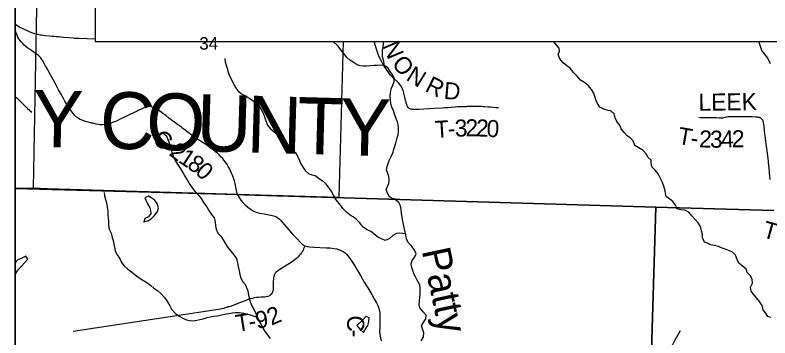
# Model space of a CAD drawing. Extents: x 0 to 34, y 0 to 22.
# Drawn here: x 1.631 to 4.145, y 15.676 to 16.751 of the extents above; entities that cross this region are included whole.
import ezdxf

# ---------------------------------------------------------------- set-up
doc = ezdxf.new("R2010")
doc.units = 0
for name, color, linetype in [('GM_X_Corporation', 7, 'Continuous'), ('GM_X_County_Road', 7, 'Continuous'), ('GM_X_County_Road_Text', 7, 'Continuous'), ('GM_X_County_Text', 7, 'Continuous'), ('GM_X_Minor_Lake', 7, 'Continuous'), ('GM_X_Minor_River', 7, 'Continuous'), ('GM_X_Minor_River_Text', 7, 'Continuous'), ('GM_X_Section_Text', 7, 'Continuous'), ('GM_X_Township_Road', 7, 'Continuous'), ('GM_X_Township_Road_Text', 7, 'Continuous'), ('SH_Data', 7, 'Continuous'), ('SH_Text', 7, 'Continuous')]:
    doc.layers.add(name, color=color, linetype=linetype)

msp = doc.modelspace()

# ---------------------------------------------------------------- linework, layer by layer
at = {"layer": 'GM_X_Corporation'}
for points in [[(8.4311, 21.3734), (1.6311, 21.3734), (1.6311, 16.1731), (2.3716, 16.1532), (2.3935, 16.1523), (3.7652, 16.1115), (4.1576, 16.1007)], [(4.7823, 18.128), (4.0508, 18.1454), (3.7812, 18.1547), (3.7776, 18.3354), (3.7807, 18.4204), (3.7875, 18.9248), (3.7889, 19.1658), (3.7877, 19.187), (3.1142, 19.2057), (2.7749, 19.2162), (2.7798, 20.0198), (2.7831, 20.242), (2.7976, 21.3075), (2.7987, 21.3734), (1.6311, 21.3734), (1.6311, 16.1731), (2.3716, 16.1532), (2.3935, 16.1523), (3.7652, 16.1115), (4.1576, 16.1007)], [(2.7241, 16.6637), (2.7088, 16.1431), (1.7396, 16.1729), (1.6922, 16.1742), (1.7115, 17.1949), (1.8974, 17.1907)], [(4.1576, 16.1007), (3.7652, 16.1115), (2.3935, 16.1523), (2.3716, 16.1532), (1.6311, 16.1731), (1.6311, 14.5734), (8.4311, 14.5734)], [(4.1576, 16.1007), (3.7652, 16.1115), (3.7495, 15.5967), (3.7461, 15.4826), (3.7459, 15.4785), (3.7348, 15.1121), (3.7347, 15.1105), (3.7221, 14.5734), (8.4311, 14.5734)]]:
    msp.add_lwpolyline(points, dxfattribs=at)
for points in [[(1.6311, 17.1972), (1.6311, 16.1758), (1.6922, 16.1742), (1.7115, 17.1949)], [(1.6311, 16.1731), (1.6311, 14.5734), (3.7221, 14.5734), (3.7347, 15.1105), (3.7348, 15.1121), (3.7459, 15.4785), (3.7461, 15.4826), (3.7495, 15.5967), (3.7652, 16.1115), (2.3935, 16.1523), (2.3716, 16.1532)]]:
    msp.add_lwpolyline(points, close=True, dxfattribs=at)
at = {"layer": 'GM_X_County_Road'}
for points in [[(1.6311, 16.7219), (1.6337, 16.7197), (1.6386, 16.716), (1.6433, 16.713), (1.6493, 16.7097), (1.6543, 16.7072), (1.6633, 16.703), (1.6718, 16.6993), (1.6799, 16.6959), (1.6886, 16.6926), (1.6962, 16.6901), (1.7028, 16.6883), (1.7095, 16.6869), (1.715, 16.6858), (1.7187, 16.6852), (1.7236, 16.6845), (1.7309, 16.6835), (1.7452, 16.6821), (1.7544, 16.6814), (1.7606, 16.6809), (1.7686, 16.6801), (1.776, 16.6794), (1.7835, 16.6787), (1.7927, 16.6778), (1.81, 16.6762), (1.8242, 16.6751), (1.8291, 16.6748), (1.8445, 16.6739), (1.8974, 16.6716)], [(2.3718, 16.1526), (2.3706, 16.1576), (2.3696, 16.1624), (2.3687, 16.1672), (2.3678, 16.172), (2.3668, 16.1775), (2.3654, 16.1842), (2.364, 16.1902), (2.3616, 16.1988), (2.3564, 16.2141), (2.3542, 16.2197), (2.3521, 16.2249), (2.3486, 16.2328), (2.345, 16.2401), (2.3411, 16.2471), (2.3373, 16.2535), (2.3324, 16.2607), (2.3268, 16.2682), (2.3228, 16.2729), (2.3178, 16.2784), (2.3123, 16.2843), (2.3064, 16.2898), (2.2988, 16.2962), (2.291, 16.3024), (2.2836, 16.308), (2.2734, 16.3151), (2.2626, 16.3222), (2.2518, 16.3292), (2.2471, 16.3322), (2.2418, 16.3354), (2.2344, 16.3401), (2.2269, 16.3455), (2.221, 16.35), (2.2195, 16.3512), (2.2077, 16.3603), (2.1929, 16.3716), (2.1869, 16.3761), (2.1849, 16.3775), (2.1758, 16.384), (2.1732, 16.3858), (2.1604, 16.3953), (2.1565, 16.3983), (2.151, 16.4024), (2.1436, 16.408), (2.1327, 16.4163), (2.1237, 16.423), (2.1132, 16.4306), (2.105, 16.4362), (2.097, 16.4411), (2.0932, 16.443), (2.088, 16.445), (2.0857, 16.4457), (2.0796, 16.4466), (2.076, 16.4466), (2.0722, 16.4462), (2.0662, 16.4445), (2.0622, 16.443), (2.0542, 16.4394), (2.0458, 16.4354), (2.0407, 16.433), (2.0374, 16.4313), (2.0128, 16.4196), (1.9972, 16.4118), (1.9816, 16.4041), (1.9686, 16.3982), (1.9594, 16.3944), (1.9524, 16.3918), (1.9453, 16.3896), (1.9381, 16.3878), (1.9307, 16.3865), (1.9227, 16.3859), (1.9146, 16.386), (1.9084, 16.3867), (1.9011, 16.388), (1.8896, 16.3906), (1.8854, 16.3917), (1.8829, 16.3922), (1.8697, 16.3955), (1.8619, 16.3979), (1.8543, 16.4006), (1.8475, 16.4035), (1.8426, 16.4062), (1.8381, 16.4095), (1.8348, 16.4123), (1.83, 16.4171), (1.8255, 16.4223), (1.821, 16.4282), (1.8156, 16.4358), (1.809, 16.4456), (1.8037, 16.454), (1.7973, 16.4647), (1.7923, 16.4732), (1.7876, 16.4813), (1.7852, 16.4856), (1.7761, 16.5025), (1.7705, 16.5129), (1.7658, 16.5217), (1.7533, 16.5446), (1.7491, 16.5522), (1.74, 16.5685), (1.737, 16.5739), (1.7352, 16.5772), (1.7339, 16.5793), (1.7279, 16.5901), (1.7223, 16.5998), (1.7211, 16.6019), (1.7184, 16.6061), (1.7157, 16.6095), (1.7128, 16.6127), (1.7087, 16.6165), (1.7028, 16.621), (1.6952, 16.6264), (1.691, 16.6291), (1.6808, 16.636), (1.6737, 16.641), (1.6669, 16.6463), (1.6614, 16.6512), (1.6565, 16.656), (1.6511, 16.662), (1.6466, 16.6679), (1.644, 16.6721), (1.6408, 16.678), (1.6379, 16.6842), (1.6338, 16.6939), (1.6311, 16.7007)], [(2.3718, 16.1526), (2.3828, 16.1351), (2.3899, 16.1265), (2.3974, 16.1186), (2.4068, 16.1109), (2.417, 16.1039), (2.4241, 16.0994), (2.4309, 16.0963), (2.437, 16.0938), (2.4456, 16.0915), (2.4526, 16.0901), (2.4607, 16.0887), (2.483, 16.0849), (2.4915, 16.083), (2.499, 16.08), (2.5057, 16.076), (2.5103, 16.0726), (2.5156, 16.068), (2.5219, 16.0608), (2.5426, 16.0363), (2.5555, 16.0217), (2.5714, 16.0044), (2.5804, 15.9947), (2.5856, 15.9897), (2.5889, 15.9867), (2.5921, 15.9844), (2.5956, 15.9825), (2.6039, 15.9803), (2.6115, 15.9794), (2.6265, 15.9781), (2.6673, 15.9761), (2.6738, 15.9758), (2.6806, 15.9754), (2.6931, 15.9741), (2.7026, 15.9722), (2.711, 15.9695), (2.7196, 15.9661), (2.7242, 15.9634), (2.7301, 15.959), (2.7352, 15.9545), (2.7398, 15.9495), (2.7443, 15.9437), (2.7494, 15.9362), (2.7533, 15.9297), (2.7621, 15.9155), (2.7716, 15.9), (2.7812, 15.884), (2.794, 15.8618), (2.8054, 15.8424), (2.819, 15.8206), (2.8286, 15.8038), (2.8347, 15.7931), (2.8393, 15.7836), (2.8416, 15.7777), (2.8437, 15.7709), (2.8451, 15.7647), (2.8459, 15.7578), (2.8462, 15.7527), (2.846, 15.7402), (2.8459, 15.7276), (2.8454, 15.7113), (2.8452, 15.6969), (2.8459, 15.687), (2.8476, 15.676), (2.8508, 15.6658)]]:
    msp.add_lwpolyline(points, dxfattribs=at)
at = {"layer": 'GM_X_Minor_Lake'}
for points in [[(2.0633, 16.142), (2.0717, 16.1227), (2.0797, 16.1095), (2.0821, 16.0997), (2.0833, 16.0899), (2.0754, 16.0792), (2.0634, 16.0734), (2.0597, 16.0617), (2.067, 16.0642)], [(2.067, 16.0642), (2.0732, 16.0663), (2.0845, 16.0728), (2.0966, 16.085), (2.1059, 16.0972), (2.1092, 16.1094), (2.1039, 16.123), (2.0943, 16.1373), (2.0848, 16.1429), (2.0753, 16.1478), (2.0633, 16.142)], [(1.6715, 15.9409), (1.6671, 15.9479), (1.6532, 15.9417), (1.6404, 15.9359), (1.6311, 15.9263)], [(1.6311, 15.8867), (1.6316, 15.8874), (1.6406, 15.9011), (1.653, 15.9144), (1.6639, 15.9266), (1.6732, 15.9381), (1.6715, 15.9409)], [(2.7946, 15.6999), (2.7971, 15.7042), (2.8054, 15.7171), (2.8095, 15.7304), (2.8099, 15.7425), (2.7996, 15.7471), (2.7883, 15.7349), (2.7698, 15.717)], [(2.7698, 15.717), (2.7805, 15.7041), (2.7915, 15.6943), (2.7946, 15.6999)]]:
    msp.add_lwpolyline(points, dxfattribs=at)
at = {"layer": 'GM_X_Minor_River'}
for points in [[(2.8995, 16.1342), (2.898, 16.1378), (2.8881, 16.1407), (2.8782, 16.1456), (2.871, 16.1577), (2.8671, 16.1706), (2.8716, 16.1801), (2.876, 16.19), (2.8775, 16.2029), (2.8762, 16.2131), (2.8724, 16.2233), (2.8681, 16.2362), (2.8707, 16.2472), (2.8737, 16.2568), (2.8766, 16.2666), (2.8837, 16.28), (2.8901, 16.2945), (2.893, 16.304), (2.896, 16.3142), (2.9001, 16.3291), (2.9041, 16.3428), (2.9067, 16.3538), (2.9081, 16.3644), (2.9077, 16.3777), (2.9053, 16.3917), (2.9006, 16.4069), (2.896, 16.4175), (2.8917, 16.4318), (2.8856, 16.4447), (2.8828, 16.4553), (2.8816, 16.4678), (2.8804, 16.4799), (2.8818, 16.4917), (2.8832, 16.505), (2.8896, 16.5176), (2.8941, 16.5298), (2.894, 16.5415), (2.8897, 16.5514), (2.8802, 16.563), (2.8721, 16.5755), (2.8607, 16.583), (2.8467, 16.584), (2.8372, 16.5836), (2.827, 16.5831), (2.8137, 16.5819), (2.8031, 16.581), (2.7917, 16.5805), (2.7807, 16.582), (2.7701, 16.5857), (2.7575, 16.5943), (2.7461, 16.6014), (2.7365, 16.6097), (2.7266, 16.6225), (2.7163, 16.635), (2.7067, 16.6474), (2.6906, 16.6637)], [(2.8603, 16.583), (2.8603, 16.5887), (2.8587, 16.5982), (2.8544, 16.6118), (2.855, 16.6323), (2.8572, 16.6467), (2.8591, 16.6637)], [(3.8348, 16.1094), (3.8311, 16.1183), (3.8216, 16.1304), (3.8113, 16.1375), (3.7991, 16.1465), (3.7971, 16.1568), (3.7963, 16.1663), (3.7916, 16.181), (3.7874, 16.1939), (3.7801, 16.209), (3.7731, 16.2219), (3.7636, 16.2339), (3.7517, 16.2456), (3.7498, 16.2585), (3.7493, 16.268), (3.7386, 16.2777), (3.7336, 16.2876), (3.7214, 16.3015), (3.7084, 16.309), (3.6955, 16.3172), (3.6901, 16.332), (3.6798, 16.3422), (3.6702, 16.3489), (3.6596, 16.3598), (3.65, 16.3723), (3.6453, 16.3848), (3.6354, 16.3972), (3.6296, 16.4093), (3.6261, 16.4222), (3.6158, 16.432), (3.6063, 16.4338), (3.5919, 16.4378), (3.579, 16.4446), (3.5705, 16.457), (3.5648, 16.4687), (3.5616, 16.4801), (3.5582, 16.4911), (3.5512, 16.5032), (3.5398, 16.5167), (3.5279, 16.5269), (3.5146, 16.5347), (3.5028, 16.5475), (3.4898, 16.5615), (3.4806, 16.5728), (3.4688, 16.5818), (3.4562, 16.5923), (3.4451, 16.6055), (3.4397, 16.6195), (3.4438, 16.6313), (3.4433, 16.6408), (3.4247, 16.6637)], [(4.147, 16.5884), (4.1423, 16.5986), (4.1366, 16.6084), (4.1285, 16.6213), (4.1182, 16.6337), (4.1085, 16.6637)], [(2.3828, 16.4899), (2.3783, 16.4933), (2.369, 16.5065), (2.361, 16.5185), (2.3536, 16.5336), (2.3467, 16.5476), (2.342, 16.56), (2.3392, 16.5698), (2.3353, 16.5831), (2.3322, 16.5944), (2.3313, 16.6069)], [(1.6311, 16.4799), (1.637, 16.476), (1.6496, 16.4629), (1.6611, 16.4509), (1.6729, 16.4396), (1.6871, 16.4277)], [(2.3828, 16.4899), (2.3921, 16.4859), (2.4046, 16.4788), (2.4183, 16.4705), (2.4313, 16.46), (2.4431, 16.4487), (2.4512, 16.4366), (2.4577, 16.4246), (2.462, 16.4124), (2.4662, 16.3992), (2.4716, 16.3848), (2.4823, 16.3728), (2.4934, 16.3637), (2.5064, 16.3528), (2.5167, 16.3431), (2.53, 16.3299), (2.5404, 16.3186), (2.5522, 16.3058), (2.5652, 16.2922), (2.5732, 16.2794), (2.5783, 16.2673), (2.5833, 16.2556), (2.5909, 16.2431), (2.5975, 16.2333), (2.6089, 16.222), (2.6195, 16.219), (2.6302, 16.2172), (2.6435, 16.2063), (2.6538, 16.2003), (2.6641, 16.1909)], [(2.2395, 16.1519), (2.2422, 16.1518), (2.2314, 16.1638), (2.2214, 16.1782), (2.2107, 16.1909), (2.2037, 16.2037), (2.1956, 16.2181), (2.1895, 16.2282), (2.1821, 16.2418), (2.1726, 16.2546), (2.1637, 16.2674), (2.1583, 16.2802), (2.1544, 16.2931), (2.1512, 16.3067), (2.1477, 16.3195), (2.1426, 16.3335), (2.136, 16.3467), (2.125, 16.3557)], [(2.6641, 16.1909), (2.6756, 16.1751), (2.6844, 16.163), (2.6905, 16.1509), (2.6981, 16.1395)], [(1.9276, 16.1605), (1.9285, 16.1496), (1.9324, 16.1364), (1.9363, 16.1212), (1.9382, 16.1102), (1.9395, 16.0996), (1.9403, 16.0852), (1.9412, 16.0754), (1.9424, 16.064), (1.9425, 16.0508), (1.9445, 16.0383), (1.9514, 16.0247), (1.9549, 16.0107), (1.9573, 16.0001), (1.96, 15.988), (1.962, 15.9782), (1.9647, 15.9661), (1.9705, 15.9532), (1.9797, 15.94), (1.9851, 15.9272), (1.9935, 15.917), (2.0057, 15.9054), (2.0186, 15.896), (2.0308, 15.8855), (2.0441, 15.8761), (2.0586, 15.8671), (2.0696, 15.8604), (2.0833, 15.8507), (2.0932, 15.842), (2.105, 15.8338), (2.118, 15.8225), (2.1298, 15.809), (2.1386, 15.7962), (2.1463, 15.7826), (2.1524, 15.7716), (2.165, 15.7566), (2.1772, 15.748), (2.1894, 15.7416), (2.2023, 15.736), (2.2121, 15.7335), (2.225, 15.7328), (2.2363, 15.7352), (2.2462, 15.7371), (2.2575, 15.7399), (2.2711, 15.7438), (2.2813, 15.7462), (2.2926, 15.7485), (2.3055, 15.7498), (2.3191, 15.7529), (2.3331, 15.7561), (2.3429, 15.7573), (2.3546, 15.7593), (2.3648, 15.7605), (2.3784, 15.7606), (2.3899, 15.7587)], [(2.2422, 16.1518), (2.2509, 16.1405), (2.259, 16.1273), (2.2701, 16.1122), (2.2762, 16.1005), (2.285, 16.0869), (2.2938, 16.0756), (2.2973, 16.0624), (2.2982, 16.0495), (2.3013, 16.0382), (2.3067, 16.0242), (2.3159, 16.0144), (2.3239, 16.002), (2.3316, 15.9888), (2.34, 15.9767), (2.3496, 15.965), (2.3595, 15.953), (2.3683, 15.9402), (2.3718, 15.9262), (2.3746, 15.9137), (2.377, 15.8997), (2.3797, 15.8876), (2.3832, 15.8755), (2.3889, 15.8632)], [(2.9319, 16.0229), (2.9116, 16.0246), (2.9018, 16.0238), (2.8889, 16.0169), (2.8765, 16.0062), (2.8632, 16.0001), (2.8488, 16.0069), (2.8394, 16.0118), (2.8257, 16.0227), (2.8155, 16.0299), (2.8018, 16.0367), (2.7889, 16.0461), (2.779, 16.059), (2.7672, 16.0714), (2.7574, 16.079), (2.7475, 16.0843), (2.7346, 16.0948), (2.7232, 16.1073), (2.7164, 16.1171), (2.7042, 16.1315), (2.6981, 16.1395)], [(3.0003, 15.7515), (2.99, 15.7629), (2.9794, 15.7765), (2.9771, 15.7863), (2.9782, 15.7977), (2.9789, 15.811), (2.9804, 15.8212), (2.9807, 15.8318), (2.9803, 15.8417), (2.9788, 15.8523), (2.9708, 15.8678), (2.9643, 15.8792), (2.9594, 15.889), (2.9559, 15.9007), (2.9513, 15.9136), (2.9502, 15.9235), (2.9536, 15.9337), (2.9626, 15.9463), (2.9664, 15.9557), (2.9618, 15.9686), (2.9511, 15.9822), (2.9398, 15.9932), (2.9352, 16.0057), (2.9329, 16.0197), (2.9287, 16.0333), (2.9264, 16.0432), (2.9244, 16.0545), (2.9225, 16.0644), (2.9202, 16.0769), (2.9183, 16.0917), (2.9167, 16.1034), (2.9152, 16.1155), (2.9094, 16.1269), (2.8995, 16.1342)], [(4.148, 15.7437), (4.1385, 15.7467), (4.1305, 15.7588), (4.1225, 15.7698), (4.1191, 15.7834), (4.1107, 15.797), (4.1008, 15.8095), (4.0902, 15.8216), (4.083, 15.8318), (4.0803, 15.8454), (4.0867, 15.858), (4.0859, 15.8712), (4.0798, 15.8833), (4.0688, 15.8935), (4.0665, 15.9053), (4.0528, 15.9162), (4.0418, 15.9245), (4.0357, 15.9366), (4.0303, 15.951), (4.0205, 15.9616), (4.0102, 15.9661), (3.9996, 15.9699), (3.9864, 15.9751), (3.9742, 15.98), (3.9602, 15.9838), (3.9473, 15.986), (3.9367, 15.9913), (3.9268, 15.995), (3.9204, 16.0087), (3.9207, 16.0212), (3.9173, 16.0329), (3.9142, 16.0465), (3.9066, 16.0594), (3.8952, 16.0711), (3.8849, 16.0828), (3.8747, 16.0946), (3.8618, 16.1017), (3.8482, 16.1028), (3.8356, 16.1062), (3.8348, 16.1094)], [(2.4818, 15.6743), (2.4719, 15.6868), (2.4643, 15.6974), (2.4578, 15.708), (2.4491, 15.7227), (2.443, 15.7352), (2.4373, 15.7485), (2.4319, 15.7617), (2.4251, 15.7734), (2.4194, 15.7837), (2.4156, 15.7954), (2.4113, 15.809), (2.4098, 15.8189), (2.4079, 15.8314), (2.4014, 15.8446), (2.3972, 15.8545), (2.3889, 15.8632)], [(2.4394, 15.7434), (2.4252, 15.748), (2.4157, 15.7518), (2.4009, 15.7548), (2.3899, 15.7587)], [(2.9831, 15.6658), (2.9918, 15.6798), (2.9929, 15.6931), (2.9891, 15.703), (2.9849, 15.7166), (2.992, 15.7291), (2.9992, 15.7394), (3.0003, 15.7515)]]:
    msp.add_lwpolyline(points, dxfattribs=at)
at = {"layer": 'GM_X_Township_Road'}
for points in [[(3.2416, 16.4418), (3.2379, 16.442), (3.2317, 16.4424), (3.215, 16.4439), (3.2052, 16.4448), (3.1934, 16.4457), (3.1897, 16.4459), (3.1854, 16.4462), (3.1792, 16.4464), (3.1705, 16.4465), (3.1562, 16.4464), (3.1413, 16.4463), (3.1382, 16.4462), (3.1364, 16.4462), (3.1339, 16.4461), (3.132, 16.4461), (3.1295, 16.446), (3.1277, 16.446), (3.1153, 16.4456), (3.1091, 16.4454), (3.1048, 16.4452), (3.0967, 16.4446), (3.0843, 16.4436), (3.072, 16.4426), (3.0614, 16.4419), (3.0552, 16.4415), (3.0282, 16.4398), (3.0102, 16.4388), (2.9929, 16.4377), (2.9762, 16.4369), (2.965, 16.4365), (2.9594, 16.4365), (2.9551, 16.4368), (2.9514, 16.4373), (2.9484, 16.4382), (2.9461, 16.4391), (2.9434, 16.4405), (2.941, 16.4425), (2.9402, 16.4434), (2.9381, 16.4465), (2.9368, 16.4492), (2.9357, 16.4522), (2.9341, 16.4582), (2.9331, 16.4618), (2.9318, 16.4672), (2.9292, 16.4775), (2.927, 16.4871), (2.926, 16.4913), (2.9242, 16.4979), (2.9227, 16.5026), (2.9209, 16.5066), (2.9194, 16.5093), (2.9165, 16.514), (2.912, 16.52), (2.9076, 16.5252), (2.9046, 16.5284), (2.8929, 16.5396), (2.8868, 16.5458), (2.8819, 16.5513), (2.8756, 16.5591), (2.8698, 16.5671), (2.8615, 16.5795), (2.8554, 16.5892), (2.8521, 16.5955), (2.8461, 16.6072), (2.8415, 16.6182), (2.8389, 16.6246), (2.8347, 16.6371), (2.8267, 16.6637)], [(4.1458, 16.204), (4.145, 16.2151), (4.1439, 16.2268), (4.1423, 16.2428), (4.1416, 16.2496), (4.1404, 16.2619), (4.1399, 16.2668), (4.1393, 16.2718), (4.1366, 16.2914), (4.1344, 16.3074), (4.1339, 16.3111), (4.1323, 16.3234), (4.1316, 16.3296), (4.1302, 16.3419), (4.1285, 16.3561), (4.1272, 16.3666), (4.1255, 16.3795), (4.1234, 16.393), (4.1227, 16.3969), (4.1222, 16.3993), (4.1215, 16.4011), (4.1204, 16.4028), (4.1187, 16.4049), (4.1174, 16.4059), (4.1162, 16.4068), (4.1149, 16.4076), (4.1135, 16.4084), (4.1118, 16.4092), (4.11, 16.4098), (4.1077, 16.4104), (4.1046, 16.4108), (4.102, 16.4112), (4.0992, 16.4114), (4.0967, 16.4115), (4.0855, 16.4118), (4.0749, 16.412), (4.0638, 16.412), (4.0495, 16.4122), (4.0371, 16.4123), (4.0235, 16.4124), (4.0165, 16.4123), (4.0111, 16.412), (4.007, 16.4118), (4.0031, 16.4113), (3.9993, 16.4106), (3.9946, 16.4096), (3.99, 16.4086), (3.9873, 16.4082), (3.9839, 16.4079), (3.9764, 16.408), (3.9676, 16.4084), (3.9595, 16.4088), (3.9546, 16.409), (3.9502, 16.4092), (3.9409, 16.4092), (3.9262, 16.4086), (3.9213, 16.4086), (3.9132, 16.4093), (3.9083, 16.4099)], [(2.5956, 15.9825), (2.5936, 15.9765), (2.5922, 15.9723), (2.5906, 15.9686), (2.5876, 15.9632), (2.5848, 15.9594), (2.5813, 15.9546), (2.5773, 15.9501), (2.5737, 15.9463), (2.569, 15.9416), (2.5639, 15.937), (2.5596, 15.9333), (2.5503, 15.927), (2.5395, 15.92), (2.5163, 15.9057), (2.5087, 15.9009), (2.501, 15.8953), (2.4971, 15.8911), (2.495, 15.8876), (2.4936, 15.8844), (2.4926, 15.8811), (2.4917, 15.8758), (2.4914, 15.8713), (2.4911, 15.8643), (2.4903, 15.8375), (2.4891, 15.8317), (2.4877, 15.8268), (2.4857, 15.8228), (2.4823, 15.8192), (2.4782, 15.816), (2.4726, 15.8133), (2.4682, 15.8123), (2.4623, 15.8118), (2.4498, 15.8111), (2.4416, 15.8106), (2.4349, 15.8099), (2.4273, 15.8091), (2.4202, 15.8075), (2.4144, 15.8059), (2.4074, 15.8034), (2.3971, 15.7997), (2.3816, 15.7939), (2.3679, 15.788), (2.3542, 15.7823), (2.3441, 15.7795), (2.3397, 15.7789), (2.3348, 15.7774)], [(2.3348, 15.7774), (2.3248, 15.7743), (2.3089, 15.7701), (1.8243, 15.6969)], [(3.6899, 15.5249), (3.6958, 15.5301), (3.6992, 15.5421), (3.7078, 15.5559), (3.7216, 15.5679), (3.7336, 15.5868), (3.7497, 15.5961), (3.7628, 15.604), (3.7869, 15.6177), (3.8006, 15.6263), (3.8212, 15.6521), (3.8298, 15.6693), (3.847, 15.7002)]]:
    msp.add_lwpolyline(points, dxfattribs=at)
at = {"layer": 'SH_Data'}
msp.add_lwpolyline([(1.8974, 16.6637), (4.5509, 16.6637), (4.5509, 17.3579), (1.8974, 17.3579)], close=True, dxfattribs=at)
at = {"layer": 'SH_Text'}
msp.add_line((1.6311, 14.5734), (1.6311, 21.3734), dxfattribs=at)

# ---------------------------------------------------------------- texts
at = {"layer": 'GM_X_County_Road_Text'}
for s, rotation, p in [('C', 322.3167, (2.0848, 16.33)), ('-', 322.4228, (2.1218, 16.3014)), ('2', 322.977, (2.1408, 16.2868)), ('1', 326.4146, (2.1718, 16.2635)), ('8', 325.135, (2.2006, 16.2444)), ('0', 317.3189, (2.2278, 16.2256)), ('C', 268.4699, (2.7379, 15.7514)), ('-', 270.0924, (2.7367, 15.703))]:
    msp.add_text(s, height=0.0568, rotation=rotation, dxfattribs=at).set_placement(p)
at = {"layer": 'GM_X_County_Text'}
for s, rotation, p in [('Y', 358.5329, (1.6866, 16.313)), ('C', 358.5322, (1.9116, 16.3073)), ('O', 358.5253, (2.0657, 16.3033)), ('U', 358.2572, (2.2329, 16.299)), ('N', 358.3498, (2.4006, 16.2939)), ('T', 358.4392, (2.5684, 16.2891)), ('Y', 358.4432, (2.71, 16.2852))]:
    msp.add_text(s, height=0.1894, rotation=rotation, dxfattribs=at).set_placement(p)
at = {"layer": 'GM_X_Minor_River_Text'}
msp.add_text('Patty', height=0.09469, rotation=282.0053, dxfattribs=at).set_placement((2.9853, 15.9669))
at = {"layer": 'GM_X_Section_Text'}
msp.add_text('34', height=0.04186, rotation=0, dxfattribs=at).set_placement((2.2449, 16.636))
at = {"layer": 'GM_X_Township_Road_Text'}
for s, height, rotation, p in [('N', 0.0568, 292.7734, (2.8543, 16.6498)), ('O', 0.0568, 309.7798, (2.8831, 16.588)), ('N', 0.0568, 328.1517, (2.9301, 16.5366)), ('R', 0.0568, 333.499, (2.9932, 16.4994)), ('D', 0.0568, 355.0626, (3.0573, 16.4723)), ('LEEK', 0.05682, 0.8062, (3.9076, 16.4322)), ('T', 0.0568, 3.6902, (3.0313, 16.3416)), ('3', 0.0568, 2.3894, (3.0966, 16.3457)), ('2', 0.0568, 0.1717, (3.131, 16.3472)), ('2', 0.0568, 357.8684, (3.1654, 16.3473)), ('0', 0.0568, 356.7587, (3.2001, 16.346)), ('-', 0.0568, 3.4054, (3.0736, 16.3444)), ('T', 0.0568, 349.9614, (3.8352, 16.323)), ('2', 0.0568, 357.7837, (3.9084, 16.3109)), ('3', 0.0568, 359.5163, (3.9453, 16.3095)), ('4', 0.0568, 2.7637, (3.9838, 16.3093)), ('2', 0.0568, 359.5212, (4.0179, 16.311)), ('-', 0.0568, 350.7298, (3.8778, 16.3154)), ('T', 0.0568, 344.5147, (4.1169, 16.0117)), ('9', 0.0568, 10.0796, (2.4365, 15.7059)), ('2', 0.0568, 23.4143, (2.4847, 15.7161)), ('T', 0.0568, 8.9156, (2.3702, 15.6954)), ('-', 0.0568, 9.1284, (2.4124, 15.702))]:
    msp.add_text(s, height=height, rotation=rotation, dxfattribs=at).set_placement(p)

doc.saveas('drawing.dxf')
